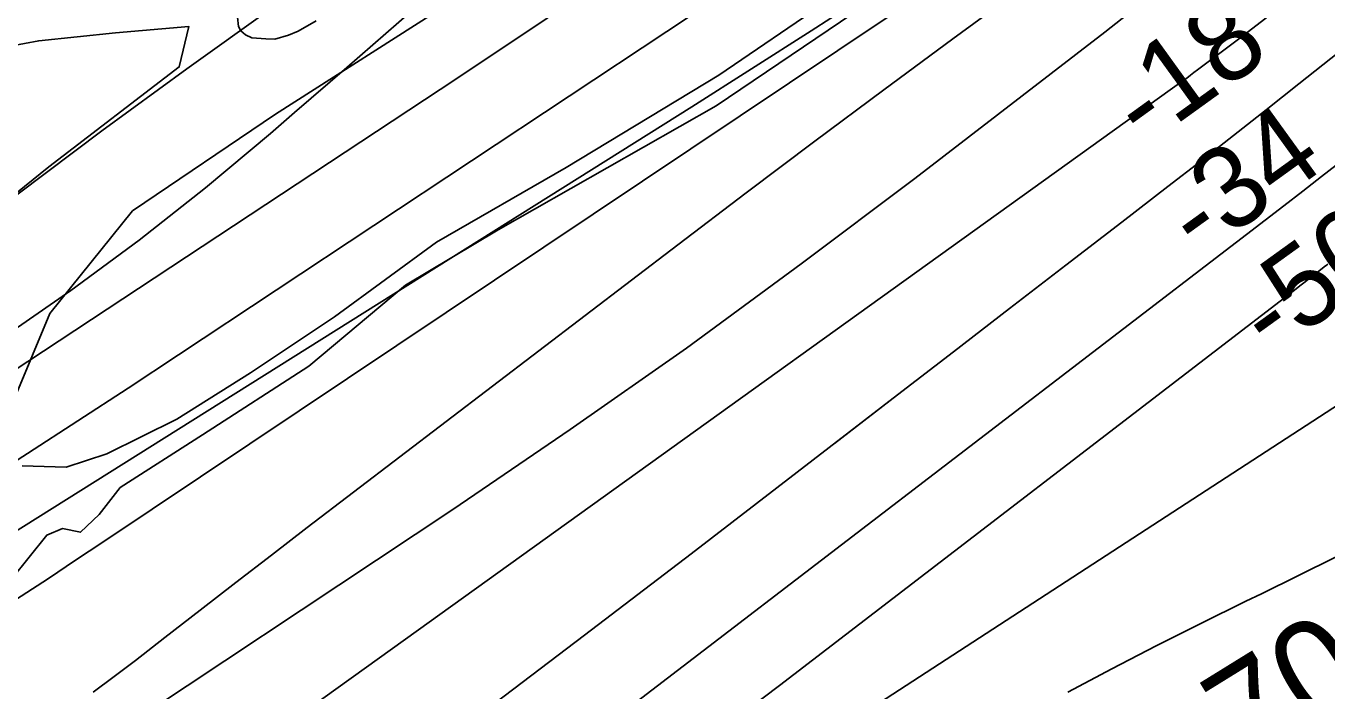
# Model space of a CAD drawing. Extents: x 3625074 to 3663148, y 511451 to 537151.
# Drawn here: x 3642410 to 3643476, y 522044 to 522589 of the extents above; entities that cross this region are included whole.
import ezdxf

# ---------------------------------------------------------------- set-up
doc = ezdxf.new("R2010")
doc.units = 0
for name, color, linetype in [('V-RIVR-EDGE', 7, 'Continuous'), ('V-RIVR-RANG', 7, 'Continuous'), ('V-SITE-VEGE', 7, 'Continuous'), ('V-TOPO-DPTH', 7, 'Continuous'), ('V-TOPO-MAJR', 7, 'Continuous'), ('V-TOPO-MINR', 7, 'Continuous'), ('V-TOPO-MINR-IDEN', 7, 'Continuous'), ('V-TOPO-WATR', 7, 'Continuous')]:
    doc.layers.add(name, color=color, linetype=linetype)

msp = doc.modelspace()

# ---------------------------------------------------------------- linework, layer by layer
at = {"layer": 'V-RIVR-EDGE'}
for points in [[(3643503.8, 522859.2), (3643380.5, 522778), (3643266.4, 522717), (3643128.9, 522627.3), (3642975.4, 522523.5), (3642796.9, 522421.6)], [(3642796.9, 522421.6), (3642720.8, 522376.4), (3642641.6, 522309.9), (3642554.4, 522253.7), (3642486.9, 522210.4), (3642469.7, 522188.3), (3642454.4, 522173.7), (3642439.7, 522176.8), (3642426.8, 522171.3), (3642397.9, 522135.2), (3642388.1, 522132.8), (3642382.6, 522142.6), (3642372.2, 522140.2), (3642339.6, 522109), (3642302.2, 522085.2), (3642257.4, 522059), (3642164.2, 522009.6), (3642062.3, 521938.1), (3641933.4, 521857), (3641814.9, 521778.2), (3641710, 521708.6)]]:
    msp.add_lwpolyline(points, dxfattribs=at)
at = {"layer": 'V-SITE-VEGE'}
for points in [[(3642385.1, 522247.4), (3642429.4, 522353.2), (3642497, 522437.2), (3642614.3, 522516.5), (3642760, 522609.4), (3642899, 522689.7), (3643022.2, 522792.2), (3643140, 522890.7), (3643242.5, 522952.4), (3643350.3, 523017.7), (3643423.2, 523062.9), (3643510.1, 523099.1)], [(3643509.3, 522941.7), (3643432.9, 522882.9), (3643338.2, 522813.5), (3643256.8, 522745.8), (3643193.7, 522690.9), (3643122.3, 522637.8), (3643065.8, 522608.7), (3642977.7, 522548.6), (3642852.6, 522472.7), (3642746.4, 522411.5), (3642662.6, 522350.3), (3642593.9, 522304.5), (3642533.5, 522266.5), (3642476, 522237.9), (3642442.8, 522227.2), (3642406.8, 522228.2)], [(3642647.6, 522593.1), (3642633, 522584.7), (3642625.1, 522581.3), (3642613.8, 522578), (3642606.3, 522578.2), (3642594.9, 522579.2), (3642589.8, 522581.7), (3642585.9, 522585), (3642584.1, 522588.4), (3642583.3, 522596.2)], [(3642361.4, 522565.8), (3642420.3, 522576.7), (3642483.2, 522583.3), (3642543.3, 522588.5), (3642535.4, 522555.3), (3642428.5, 522473.3), (3642388.6, 522441)]]:
    msp.add_lwpolyline(points, dxfattribs=at)
at = {"layer": 'V-TOPO-DPTH'}
for points in [[(3644972.2, 523916.7), (3644897.9, 523850.8), (3644837.6, 523796.8), (3644777.6, 523742.6), (3644717.9, 523688), (3644658.5, 523633.1), (3644250.3, 523253.3), (3644247.3, 523250.5), (3644246, 523249.3), (3644245.9, 523249.2), (3644245.9, 523249.2), (3643484.8, 522641.3), (3643464.9, 522625.6), (3643444.9, 522609.9), (3643424.8, 522594.4), (3643404.7, 522579), (3643370.1, 522552.8), (3643367.1, 522550.6), (3643364.2, 522548.4), (3643361.2, 522546.2), (3643358.3, 522544.1), (3642720.8, 522086), (3642676.3, 522054.1), (3642631.9, 522022.2)], [(3644972.2, 523916.7), (3644897.9, 523850.8), (3644837.6, 523796.8), (3644777.6, 523742.6), (3644717.9, 523688), (3644658.5, 523633.1), (3644250.3, 523253.3), (3644247.3, 523250.5), (3644246, 523249.3), (3644245.9, 523249.2), (3644245.9, 523249.2), (3643484.8, 522641.3), (3643464.9, 522625.6), (3643444.9, 522609.9), (3643424.8, 522594.4), (3643404.7, 522579), (3643370.1, 522552.8), (3643367.1, 522550.6), (3643364.2, 522548.4), (3643361.2, 522546.2), (3643358.3, 522544.1), (3642720.8, 522086), (3642676.3, 522054.1), (3642631.9, 522022.2)], [(3644952.9, 523717.4), (3644697.3, 523474.3), (3644636.9, 523417.6), (3644575.9, 523361.5), (3644514.1, 523306.3), (3644451.7, 523251.8), (3644351, 523164.9), (3644338.5, 523154.3), (3644326, 523143.7), (3644313.3, 523133.3), (3644300.6, 523122.9), (3643996.3, 522877.7), (3643904.5, 522804), (3643812.4, 522730.8), (3643719.8, 522658.1), (3643627, 522585.7), (3643471.7, 522465.3), (3643456.3, 522453.4), (3643440.9, 522441.5), (3643425.5, 522429.7), (3643410.1, 522417.8), (3642843.4, 521983.4)], [(3642843.4, 521983.4), (3643410.1, 522417.8), (3643425.5, 522429.7), (3643440.9, 522441.5), (3643456.3, 522453.4), (3643471.7, 522465.3), (3643627, 522585.7), (3643719.8, 522658.1), (3643812.4, 522730.8), (3643904.5, 522804), (3643996.3, 522877.7), (3644300.6, 523122.9), (3644313.3, 523133.3), (3644326, 523143.7), (3644338.5, 523154.3), (3644351, 523164.9), (3644451.7, 523251.8), (3644514.1, 523306.3), (3644575.9, 523361.5), (3644636.9, 523417.6), (3644697.3, 523474.3), (3644952.9, 523717.4)], [(3642051.9, 521955.5), (3642263.7, 522088.1), (3642287.9, 522103.3), (3642312.1, 522118.5), (3642336.4, 522133.7), (3642360.6, 522148.9), (3642955.5, 522522.6), (3643004.5, 522553.6), (3643053.3, 522584.8), (3643101.8, 522616.2), (3643150.3, 522648), (3643241.8, 522708.2), (3643244.4, 522710), (3643247, 522711.7), (3643249.5, 522713.5), (3643252.1, 522715.3), (3643299.8, 522749.7), (3643326.1, 522768.8), (3643352.4, 522788), (3643378.5, 522807.4), (3643404.5, 522826.9), (3644116.5, 523364.1)], [(3644116.5, 523364.1), (3643404.5, 522826.9), (3643378.5, 522807.4), (3643352.4, 522788), (3643326.1, 522768.8), (3643299.8, 522749.7), (3643252.1, 522715.3), (3643249.5, 522713.5), (3643247, 522711.7), (3643244.4, 522710), (3643241.8, 522708.2), (3643150.3, 522648), (3643101.8, 522616.2), (3643053.3, 522584.8), (3643004.5, 522553.6), (3642955.5, 522522.6), (3642360.6, 522148.9), (3642336.4, 522133.7), (3642312.1, 522118.5), (3642287.9, 522103.3), (3642263.7, 522088.1), (3642051.9, 521955.5)], [(3642464.8, 522042.5), (3642482.2, 522055.4), (3642499.5, 522068.6), (3642523.5, 522087.3), (3642552.6, 522109.9), (3642581.8, 522132.5), (3642611.1, 522155), (3642640.4, 522177.5), (3642944, 522409.4), (3643000.1, 522452), (3643056.3, 522494.4), (3643112.8, 522536.4), (3643169.4, 522578.3), (3643228.2, 522621.5), (3643255.5, 522641.6), (3643282.8, 522661.8), (3643309.9, 522682.1), (3643337, 522702.5), (3644006.1, 523206.4)], [(3644006.1, 523206.4), (3643337, 522702.5), (3643309.9, 522682.1), (3643282.8, 522661.8), (3643255.5, 522641.6), (3643228.2, 522621.5), (3643169.4, 522578.3), (3643112.8, 522536.4), (3643056.3, 522494.4), (3643000.1, 522452), (3642944, 522409.4), (3642640.4, 522177.5), (3642611.1, 522155), (3642581.8, 522132.5), (3642552.6, 522109.9), (3642523.5, 522087.3), (3642499.5, 522068.6), (3642482.2, 522055.4), (3642464.8, 522042.5)], [(3641530.3, 521789.6), (3642211, 522185), (3642232, 522197.4), (3642252.8, 522210.1), (3642273.5, 522223.1), (3642293.9, 522236.3), (3642749.4, 522536.7), (3642819.6, 522583.5), (3642889.4, 522630.9), (3642958.6, 522679.2), (3643027.5, 522727.9), (3643136.5, 522806), (3643150.7, 522816), (3643165, 522825.9), (3643179.4, 522835.5), (3643194, 522845.1), (3643320.3, 522926.3), (3643397.8, 522976.8), (3643475, 523027.8), (3643551.5, 523079.7)], [(3642780.1, 522023), (3642867.7, 522089.4), (3642954.9, 522156.1), (3643042, 522223), (3643124.1, 522286.3), (3643170.1, 522321.7), (3643216, 522357.1), (3643262, 522392.6), (3643307.9, 522428), (3643345.8, 522457.3), (3643372.7, 522478.1), (3643399.6, 522499.1), (3643426.4, 522520.1), (3643453.1, 522541.3), (3643811.3, 522825.3)], [(3642780.1, 522023), (3642867.7, 522089.4), (3642954.9, 522156.1), (3643042, 522223), (3643124.1, 522286.3), (3643170.1, 522321.7), (3643216, 522357.1), (3643262, 522392.6), (3643307.9, 522428), (3643345.8, 522457.3), (3643372.7, 522478.1), (3643399.6, 522499.1), (3643426.4, 522520.1), (3643453.1, 522541.3), (3643811.3, 522825.3)]]:
    msp.add_lwpolyline(points, dxfattribs=at)
at = {"layer": 'V-TOPO-MAJR'}
msp.add_lwpolyline([(3643476.8, 522393.5), (3643475.4, 522392.4), (3643475, 522392.1), (3643467.1, 522385.9), (3643462.7, 522382.5), (3643458.3, 522379.1), (3643453.9, 522375.7), (3643449.5, 522372.3), (3643027.4, 522048.1), (3642952.6, 521991.5)], dxfattribs=at)
at = {"layer": 'V-TOPO-MINR'}
for points in [[(3644972.2, 523916.7), (3644897.9, 523850.8), (3644837.6, 523796.8), (3644777.6, 523742.6), (3644717.9, 523688), (3644658.5, 523633.1), (3644250.3, 523253.3), (3644247.3, 523250.5), (3644246, 523249.3), (3644245.9, 523249.2), (3644245.9, 523249.2), (3643484.8, 522641.3), (3643464.9, 522625.6), (3643444.9, 522609.9), (3643424.8, 522594.4), (3643404.7, 522579), (3643370.1, 522552.8), (3643367.1, 522550.6), (3643364.2, 522548.4), (3643361.2, 522546.2), (3643358.3, 522544.1), (3642720.8, 522086), (3642676.3, 522054.1), (3642631.9, 522022.2)], [(3644952.9, 523717.4), (3644697.3, 523474.3), (3644636.9, 523417.6), (3644575.9, 523361.5), (3644514.1, 523306.3), (3644451.7, 523251.8), (3644351, 523164.9), (3644338.5, 523154.3), (3644326, 523143.7), (3644313.3, 523133.3), (3644300.6, 523122.9), (3643996.3, 522877.7), (3643904.5, 522804), (3643812.4, 522730.8), (3643719.8, 522658.1), (3643627, 522585.7), (3643471.7, 522465.3), (3643456.3, 522453.4), (3643440.9, 522441.5), (3643425.5, 522429.7), (3643410.1, 522417.8), (3642843.4, 521983.4)], [(3644973.1, 523329.9), (3644871, 523258.8), (3644768.6, 523188.2), (3644666, 523117.9), (3644505, 523008.4), (3644482.7, 522993), (3644460.5, 522977.6), (3644438.4, 522962), (3644416.4, 522946.3), (3643540.6, 522314.4), (3643538.7, 522313.1), (3643534.9, 522310.4), (3643531, 522307.9), (3643530.2, 522307.4), (3642618.3, 521714.6)], [(3643969.3, 523291.5), (3643240.9, 522788.3), (3643224.5, 522777.1), (3643208.1, 522765.9), (3643191.6, 522754.8), (3643175.1, 522743.7), (3642534.9, 522319.2), (3642493.7, 522292), (3642452.4, 522265), (3642411, 522238.2), (3642369.4, 522211.6), (3642294.2, 522163.6), (3642290.2, 522161.1), (3642286.2, 522158.5), (3642282.2, 522156), (3642278.2, 522153.5), (3642115, 522051.8), (3642029.3, 521998.5)], [(3643516.4, 523249.2), (3643108.8, 522953.9), (3643097, 522945.5), (3643085.2, 522937), (3643073.4, 522928.6), (3643061.6, 522920.3), (3642611.6, 522603.8), (3642541.6, 522553.7), (3642472, 522503), (3642403.3, 522451.2), (3642335, 522398.7), (3642238.5, 522323.2), (3642218.8, 522308.1), (3642198.8, 522293.3), (3642178.6, 522278.8), (3642158.2, 522264.7), (3642024.5, 522173.7), (3641936.2, 522115.6), (3641846.8, 522059.4), (3641755.8, 522005.8)], [(3644006.1, 523206.4), (3643337, 522702.5), (3643309.9, 522682.1), (3643282.8, 522661.8), (3643255.5, 522641.6), (3643228.2, 522621.5), (3643169.4, 522578.3), (3643112.8, 522536.4), (3643056.3, 522494.4), (3643000.1, 522452), (3642944, 522409.4), (3642640.4, 522177.5), (3642611.1, 522155), (3642581.8, 522132.5), (3642552.6, 522109.9), (3642523.5, 522087.3), (3642499.5, 522068.6), (3642482.2, 522055.4), (3642464.8, 522042.5)], [(3643478.8, 523135.2), (3643413.5, 523098.8), (3643349.6, 523060.1), (3643286.5, 523019.9), (3643133.9, 522918.7), (3643121.9, 522910.7), (3643110, 522902.5), (3643098.2, 522894.2), (3643086.4, 522885.9), (3642976.9, 522807.2), (3642931.5, 522773.6), (3642886.8, 522739.1), (3642843.2, 522703.3), (3642800.2, 522666.6), (3642757.8, 522629.3), (3642715.3, 522592), (3642672.7, 522554.9), (3642630, 522517.8), (3642610.3, 522500.7), (3642557, 522456.2), (3642502.6, 522413.1), (3642446.7, 522372), (3642389.6, 522332.3)], [(3643551.5, 523079.7), (3643475, 523027.8), (3643397.8, 522976.8), (3643320.3, 522926.3), (3643194, 522845.1), (3643179.4, 522835.5), (3643165, 522825.9), (3643150.7, 522816), (3643136.5, 522806), (3643027.5, 522727.9), (3642958.6, 522679.2), (3642889.4, 522630.9), (3642819.6, 522583.5), (3642749.4, 522536.7), (3642293.9, 522236.3), (3642273.5, 522223.1), (3642252.8, 522210.1), (3642232, 522197.4), (3642211, 522185), (3641530.3, 521789.6)], [(3643499.5, 522866.4), (3643284.1, 522710.2), (3643272.2, 522701.7), (3643260.2, 522693.2), (3643248.2, 522684.9), (3643236.1, 522676.7), (3642472.7, 522165.5), (3642450.5, 522150.7), (3642428.2, 522135.9), (3642405.9, 522121.3), (3642383.5, 522106.7), (3642343.4, 522080.8), (3642341, 522079.3), (3642338.6, 522077.7), (3642336.1, 522076.2), (3642333.7, 522074.7), (3642245, 522019.8)], [(3643811.3, 522825.3), (3643453.1, 522541.3), (3643426.4, 522520.1), (3643399.6, 522499.1), (3643372.7, 522478.1), (3643345.8, 522457.3), (3643307.9, 522428), (3643262, 522392.6), (3643216, 522357.1), (3643170.1, 522321.7), (3643124.1, 522286.3), (3643072.5, 522246.5)], [(3643548.5, 522785.2), (3643473.3, 522725.5), (3643351.3, 522628.6), (3643337, 522617.3), (3643322.8, 522606.1), (3643308.4, 522595), (3643294.1, 522583.8), (3643138.2, 522463.8), (3643045.2, 522393.7), (3642951.2, 522324.8), (3642855.9, 522258), (3642759.6, 522192.5), (3642448.6, 521985.6)], [(3643483.1, 522153.3), (3643452.9, 522138.2), (3643422.5, 522123.3), (3643409.6, 522117.1), (3643372.8, 522099), (3643336.2, 522080.6), (3643299.9, 522061.7), (3643263.7, 522042.5)]]:
    msp.add_lwpolyline(points, dxfattribs=at)
at = {"layer": 'V-TOPO-WATR'}
msp.add_lwpolyline([(3644116.5, 523364.1), (3643404.5, 522826.9), (3643378.5, 522807.4), (3643352.4, 522788), (3643326.1, 522768.8), (3643299.8, 522749.7), (3643252.1, 522715.3), (3643249.5, 522713.5), (3643247, 522711.7), (3643244.4, 522710), (3643241.8, 522708.2), (3643150.3, 522648), (3643101.8, 522616.2), (3643053.3, 522584.8), (3643004.5, 522553.6), (3642955.5, 522522.6), (3642360.6, 522148.9), (3642336.4, 522133.7), (3642312.1, 522118.5), (3642287.9, 522103.3), (3642263.7, 522088.1), (3642051.9, 521955.5)], dxfattribs=at)

# ---------------------------------------------------------------- texts
at = {"layer": 'V-RIVR-RANG'}
for s, p in [('-18', (3643326.7, 522489)), ('-34', (3643371.6, 522398)), ('-50', (3643430.3, 522317.1))]:
    msp.add_text(s, height=67, rotation=35.8126, dxfattribs=at).set_placement(p)
at = {"layer": 'V-TOPO-MINR-IDEN'}
msp.add_text('-70', height=83, rotation=31.7427, dxfattribs=at).set_placement((3643379.3, 521957.2))

doc.saveas('drawing.dxf')
